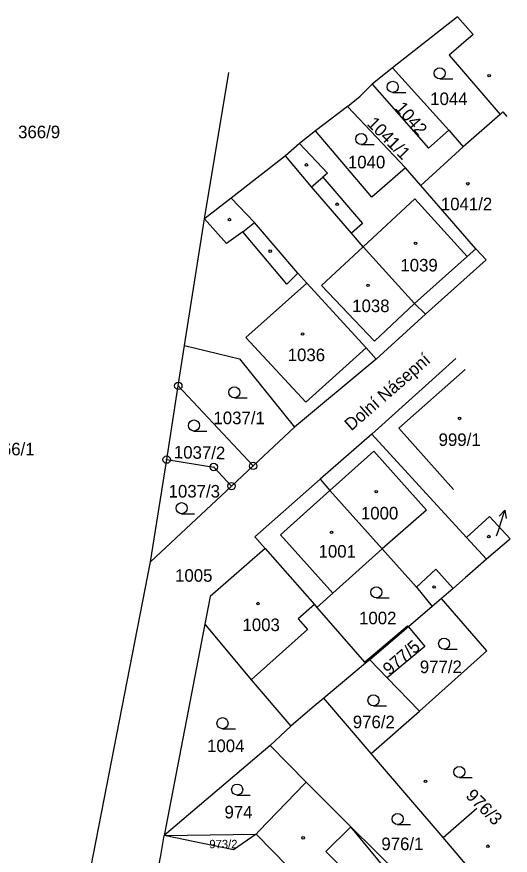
# Model space of a CAD drawing. Extents: x -776701 to -776081, y -974398 to -973771.
# Drawn here: x -776147.4 to -776080.6, y -973884.4 to -973770.9 of the extents above; entities that cross this region are included whole.
import ezdxf

# ---------------------------------------------------------------- set-up
doc = ezdxf.new("R2010")
doc.units = 0
for name, color, linetype in [('Hranice parcel', 7, 'Continuous'), ('Parcelní čísla', 7, 'Continuous'), ('Pop  PČ popisy', 7, 'Continuous'), ('Vnitřní kresba', 7, 'Continuous'), ('Značky bodu BP', 7, 'Continuous'), ('Značky budov', 7, 'Continuous'), ('Značky kultur', 7, 'Continuous')]:
    doc.layers.add(name, color=color, linetype=linetype)

msp = doc.modelspace()

# ---------------------------------------------------------------- linework, layer by layer
at = {"layer": 'Hranice parcel'}
for p, q in [((-776087.73, -973770.86), (-776096.54, -973777.78)), ((-776085.59, -973773.24), (-776087.73, -973770.86)), ((-776121.96, -973798.2), (-776118.66, -973778.41)), ((-776096.54, -973777.78), (-776099.26, -973779.99)), ((-776088.9, -973786.2), (-776096.54, -973777.78)), ((-776102.6, -973783), (-776106.93, -973786.31)), ((-776094.77, -973791.29), (-776102.6, -973783)), ((-776081.97, -973784.07), (-776086.96, -973788.46)), ((-776088.9, -973786.2), (-776086.96, -973788.46)), ((-776092.69, -973793.7), (-776086.96, -973788.46)), ((-776111, -973789.7), (-776118.34, -973795.41)), ((-776092.69, -973793.7), (-776094.77, -973791.29)), ((-776085.24, -973802.29), (-776092.69, -973793.7)), ((-776118.34, -973795.41), (-776121.96, -973798.2)), ((-776124.66, -973815.37), (-776121.96, -973798.2)), ((-776083.83, -973803.78), (-776085.24, -973802.29)), ((-776083.83, -973803.78), (-776092.08, -973811.12)), ((-776092.08, -973811.12), (-776098.72, -973817.22)), ((-776125.52, -973820.83), (-776124.66, -973815.37)), ((-776098.72, -973817.22), (-776109.8, -973826.43)), ((-776087.97, -973817.1), (-776099.33, -973827.35)), ((-776127.09, -973830.81), (-776125.52, -973820.83)), ((-776125.52, -973820.83), (-776115.39, -973831.66)), ((-776109.8, -973826.43), (-776115.39, -973831.66)), ((-776099.33, -973827.35), (-776106.3, -973833.44)), ((-776099.33, -973827.35), (-776086.53, -973841.36)), ((-776129.26, -973844.64), (-776127.09, -973830.81)), ((-776115.39, -973831.66), (-776118.31, -973834.39)), ((-776118.31, -973834.39), (-776129.26, -973844.64)), ((-776086.53, -973841.36), (-776083.8, -973844.3)), ((-776080.78, -973841.71), (-776083.8, -973844.3)), ((-776080.59, -973841.55), (-776080.78, -973841.71)), ((-776089.89, -973849.61), (-776091.15, -973850.7)), ((-776091.15, -973850.7), (-776094.38, -973853.43)), ((-776121.93, -973853.09), (-776127.43, -973881.7)), ((-776094.38, -973853.43), (-776099.59, -973857.91)), ((-776083.74, -973856.71), (-776092.89, -973864.85)), ((-776099.59, -973857.91), (-776100.2, -973858.35)), ((-776097.23, -973860.37), (-776099.59, -973857.91)), ((-776100.2, -973858.35), (-776105.82, -973863.11)), ((-776092.89, -973864.85), (-776097.23, -973860.37)), ((-776099.43, -973870.57), (-776105.82, -973863.11)), ((-776099.43, -973870.57), (-776092.89, -973864.85)), ((-776110.3, -973866.9), (-776113.08, -973869.51)), ((-776113.08, -973869.51), (-776127.43, -973881.7)), ((-776108.19, -973874.45), (-776113.08, -973869.51)), ((-776098.69, -973871.44), (-776099.43, -973870.57)), ((-776108.19, -973874.45), (-776102.18, -973880.53)), ((-776092.25, -973892.45), (-776102.18, -973880.53)), ((-776102.18, -973880.53), (-776091.04, -973891.43)), ((-776127.43, -973881.7), (-776115, -973881.5))]:
    msp.add_line(p, q, dxfattribs=at)
for points in [[(-776085.59, -973773.24), (-776088.87, -973776.08), (-776081.97, -973784.07)], [(-776102.6, -973783), (-776100.9, -973781.6), (-776099.26, -973779.99)], [(-776099.26, -973779.99), (-776091.65, -973788.65), (-776088.9, -973786.2)], [(-776106.93, -973786.31), (-776109.1, -973788), (-776111, -973789.7)], [(-776094.77, -973791.29), (-776099.3, -973795.3), (-776106.93, -973786.31)], [(-776092.08, -973811.12), (-776093.56, -973809.67), (-776100.5, -973802), (-776102.09, -973800.15), (-776107.47, -973793.87), (-776111, -973789.7)], [(-776098.72, -973817.22), (-776100.11, -973815.66), (-776108.11, -973806.91), (-776109.32, -973805.55), (-776115.2, -973798.7), (-776118.34, -973795.41)], [(-776124.66, -973815.37), (-776117.22, -973817.18), (-776109.8, -973826.43)], [(-776127.09, -973830.81), (-776120.72, -973831.81), (-776118.31, -973834.39)], [(-776106.3, -973833.44), (-776115.15, -973841.25), (-776113.75, -973842.83)], [(-776106.3, -973833.44), (-776105.01, -973834.98), (-776097.91, -973842.9)], [(-776086.53, -973841.36), (-776083.4, -973838.49), (-776080.59, -973841.55)], [(-776113.75, -973842.83), (-776121.2, -973849.36), (-776121.93, -973853.09)], [(-776113.75, -973842.83), (-776107.1, -973850.43), (-776106.77, -973850.81)], [(-776106.77, -973850.81), (-776104.61, -973848.88), (-776097.91, -973842.9)], [(-776097.91, -973842.9), (-776093.27, -973848.07), (-776091.15, -973850.7)], [(-776083.8, -973844.3), (-776086.08, -973846.28), (-776086.63, -973846.77)], [(-776144.3, -973934.4), (-776145.69, -973928.87), (-776129.26, -973844.64)], [(-776086.63, -973846.77), (-776088.32, -973848.25), (-776089.89, -973849.61)], [(-776083.74, -973856.71), (-776084.01, -973856.39), (-776089.89, -973849.61)], [(-776106.77, -973850.81), (-776100.31, -973858.22), (-776100.2, -973858.35)], [(-776121.93, -973853.09), (-776115.65, -973860.6), (-776110.3, -973866.9)], [(-776094.38, -973853.43), (-776092.13, -973856.1), (-776097.23, -973860.37)], [(-776105.82, -973863.11), (-776107.4, -973864.4), (-776110.3, -973866.9)], [(-776080.71, -973892.46), (-776081.89, -973891.08), (-776085.65, -973886.69), (-776089.68, -973881.97), (-776098.69, -973871.44)], [(-776115, -973881.5), (-776114.61, -973881.1), (-776108.39, -973874.65), (-776108.19, -973874.45)], [(-776092.78, -973903.83), (-776107.89, -973890.94), (-776103.16, -973886.26), (-776105.53, -973883.85), (-776102.18, -973880.53)], [(-776129.79, -973894.18), (-776127.86, -973884.42), (-776127.43, -973881.7)], [(-776115, -973881.5), (-776118.04, -973883.63), (-776127.43, -973881.7)]]:
    msp.add_lwpolyline(points, dxfattribs=at)
at = {"layer": 'Pop  PČ popisy'}
for p, q in [((-776082.24, -973840.52), (-776081.31, -973837.67)), ((-776081.31, -973837.67), (-776082.1, -973838.46)), ((-776081.31, -973837.67), (-776081.15, -973838.77)), ((-776082.43, -973841.13), (-776082.24, -973840.52))]:
    msp.add_line(p, q, dxfattribs=at)
at = {"layer": 'Vnitřní kresba'}
for p, q in [((-776081.97, -973784.07), (-776081.59, -973783.74)), ((-776081.59, -973783.74), (-776081.06, -973784.34)), ((-776109.1, -973788), (-776105.33, -973792.04)), ((-776105.33, -973792.04), (-776105.95, -973792.57)), ((-776107.47, -973793.87), (-776105.95, -973792.57)), ((-776105.95, -973792.57), (-776100.57, -973798.84)), ((-776100.5, -973802), (-776093.5, -973795.5)), ((-776093.5, -973795.5), (-776086.41, -973803.31)), ((-776119, -973801.55), (-776121.96, -973798.2)), ((-776116.8, -973799.99), (-776115.2, -973798.7)), ((-776100.57, -973798.84), (-776102.09, -973800.15)), ((-776116.8, -973799.99), (-776119, -973801.55)), ((-776110.84, -973807.07), (-776116.8, -973799.99)), ((-776106.13, -973807.23), (-776100.5, -973802)), ((-776085.24, -973802.29), (-776086.41, -973803.31)), ((-776086.41, -973803.31), (-776093.56, -973809.67)), ((-776109.32, -973805.55), (-776110.84, -973807.07)), ((-776108.11, -973806.91), (-776116.36, -973814.28)), ((-776098.96, -973814.79), (-776106.13, -973807.23)), ((-776093.56, -973809.67), (-776098.96, -973814.79)), ((-776116.36, -973814.28), (-776108.25, -973823.01)), ((-776108.25, -973823.01), (-776100.11, -973815.66)), ((-776095.68, -973826.57), (-776086.71, -973818.59)), ((-776088.25, -973834.84), (-776095.68, -973826.57)), ((-776105.01, -973834.98), (-776099.07, -973829.66)), ((-776099.07, -973829.66), (-776091.92, -973837.67)), ((-776111.69, -973840.97), (-776105.01, -973834.98)), ((-776091.92, -973837.67), (-776097.91, -973842.9)), ((-776104.61, -973848.88), (-776111.69, -973840.97)), ((-776093.27, -973848.07), (-776090.65, -973845.65)), ((-776090.65, -973845.65), (-776088.32, -973848.25)), ((-776107.1, -973850.43), (-776109.28, -973852.34)), ((-776109.28, -973852.34), (-776108.01, -973853.79)), ((-776100.31, -973858.22), (-776094.49, -973853.31)), ((-776094.38, -973853.43), (-776094.49, -973853.31)), ((-776108.01, -973853.79), (-776115.65, -973860.6)), ((-776089.68, -973881.97), (-776085.09, -973878)), ((-776115, -973881.5), (-776110.7, -973885.9))]:
    msp.add_line(p, q, dxfattribs=at)
at = {"layer": 'Značky bodu BP'}
for centre, radius in [((-776125.52, -973820.83), 0.5), ((-776125.52, -973820.83), 0.0303), ((-776127.09, -973830.81), 0.5), ((-776127.09, -973830.81), 0.0303), ((-776120.72, -973831.81), 0.5), ((-776120.72, -973831.81), 0.0303), ((-776115.39, -973831.66), 0.5), ((-776115.39, -973831.66), 0.0303), ((-776118.31, -973834.39), 0.5), ((-776118.31, -973834.39), 0.0303)]:
    msp.add_circle(centre, radius, dxfattribs=at)
at = {"layer": 'Značky budov'}
for centre in [(-776083.45, -973778.83), (-776108.18, -973790.92), (-776086.33, -973793.46), (-776104.01, -973796.24), (-776118.6, -973798.32), (-776093.4, -973801.53), (-776113.07, -973802.6), (-776099.84, -973807.22), (-776108.69, -973813.8), (-776087.44, -973825.23), (-776098.72, -973835.15), (-776104.77, -973840.65), (-776083.49, -973841.23), (-776090.9, -973848.05), (-776114.73, -973850.3), (-776092.06, -973874.36), (-776108.61, -973882.01), (-776083.61, -973883.15)]:
    msp.add_circle(centre, 0.175, dxfattribs=at)
at = {"layer": 'Značky kultur'}
for p, q in [((-776090.13, -973779.26), (-776088.38, -973779.26)), ((-776096.49, -973781.1), (-776094.74, -973781.1)), ((-776100.76, -973788.16), (-776099.01, -973788.16)), ((-776117.93, -973822.44), (-776116.18, -973822.44)), ((-776123.4, -973826.94), (-776121.65, -973826.94)), ((-776125.07, -973838.13), (-776123.32, -973838.13)), ((-776098.71, -973849.52), (-776096.96, -973849.52)), ((-776089.54, -973856.47), (-776087.79, -973856.47)), ((-776099.1, -973864.15), (-776097.35, -973864.15)), ((-776119.53, -973867.24), (-776117.78, -973867.24)), ((-776087.47, -973873.84), (-776085.72, -973873.84)), ((-776117.55, -973876.22), (-776115.8, -973876.22)), ((-776095.83, -973880.2), (-776094.08, -973880.2))]:
    msp.add_line(p, q, dxfattribs=at)
for centre in [(-776090.13, -973778.51), (-776096.49, -973780.35), (-776100.76, -973787.41), (-776117.93, -973821.69), (-776123.4, -973826.19), (-776125.07, -973837.38), (-776098.71, -973848.77), (-776089.54, -973855.72), (-776099.1, -973863.4), (-776119.53, -973866.49), (-776087.47, -973873.09), (-776117.55, -973875.47), (-776095.83, -973879.45)]:
    msp.add_circle(centre, 0.75, dxfattribs=at)

# ---------------------------------------------------------------- texts
at = {"layer": 'Parcelní čísla'}
for s, height, p in [('1044', 1.7, (-776091.42, -973782.81)), ('366/9', 1.7, (-776147.2, -973787.3)), ('1040', 1.7, (-776102.56, -973791.38)), ('1041/2', 1.7, (-776089.98, -973797.06)), ('1039', 1.7, (-776095.46, -973805.34)), ('1038', 1.7, (-776101.98, -973810.84)), ('1036', 1.7, (-776110.71, -973817.48)), ('1037/1', 1.7, (-776120.76, -973826.01)), ('999/1', 1.7, (-776090.28, -973828.96)), ('366/1', 1.7, (-776150.66, -973830.23)), ('1037/3', 1.7, (-776126.83, -973835.94)), ('1000', 1.7, (-776100.8, -973838.91)), ('1001', 1.7, (-776106.53, -973844.07)), ('1005', 1.7, (-776125.95, -973847.34)), ('1002', 1.7, (-776101.05, -973853.1)), ('1003', 1.7, (-776116.83, -973854.02)), ('977/2', 1.7, (-776092.83, -973859.71)), ('976/2', 1.7, (-776101.9, -973867.17)), ('1004', 1.7, (-776121.62, -973870.4)), ('974', 1.7, (-776119.26, -973879.38)), ('973/2', 1.139, (-776121.32, -973883.42)), ('976/1', 1.7, (-776098.03, -973883.67))]:
    msp.add_text(s, height=height, dxfattribs=at).set_placement(p)
for s, rotation, p in [('1042', 311, (-776096.28, -973783.27)), ('1041/1', 315, (-776100.07, -973785.43)), ('1037/2', 359, (-776126.13, -973830.64)), ('977/5', 41, (-776096.93, -973860.1)), ('976/3', 315, (-776086.73, -973876.42))]:
    msp.add_text(s, height=1.7, rotation=rotation, dxfattribs=at).set_placement(p)
at = {"layer": 'Pop  PČ popisy'}
msp.add_text('Dolní Násepní', height=1.7, rotation=41, dxfattribs=at).set_placement((-776102.11, -973827))

doc.saveas('drawing.dxf')
